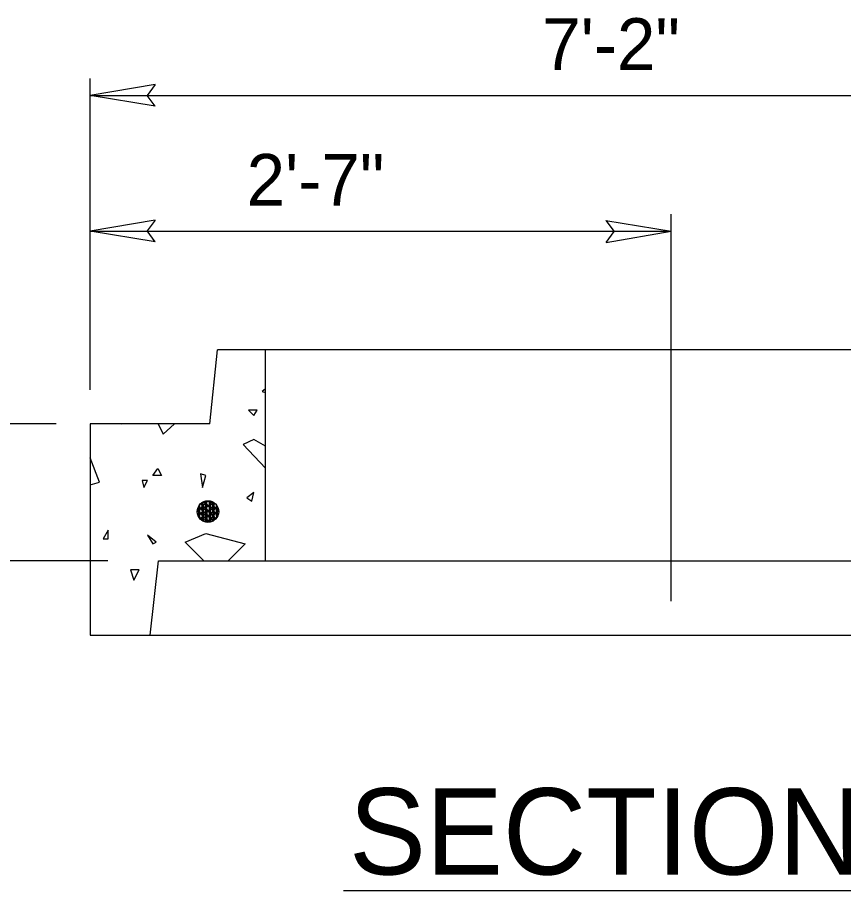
# Model space of a CAD drawing. Extents: x 1.8 to 9.1, y -6 to 4.
# Drawn here: x 5.032 to 5.989, y 0.893 to 1.904 of the extents above; entities that cross this region are included whole.
import ezdxf

# ---------------------------------------------------------------- set-up
doc = ezdxf.new("R2010")
doc.units = 0
for name, color, linetype in [('DETL-DIMS', 7, 'Continuous'), ('DETL-LINE', 7, 'Continuous'), ('DETL-NOTE', 7, 'Continuous'), ('DETL-PATT', 7, 'Continuous'), ('DETL-TITL', 7, 'Continuous')]:
    doc.layers.add(name, color=color, linetype=linetype)

msp = doc.modelspace()

# ---------------------------------------------------------------- linework, layer by layer
at = {"layer": 'DETL-DIMS'}
for p, q in [((5.1159, 1.4731), (5.1159, 1.8337)), ((5.1913, 1.8268), (5.1159, 1.8141)), ((5.1913, 1.8268), (5.1819, 1.8142)), ((5.1914, 1.8017), (5.1159, 1.8141)), ((5.1159, 1.8141), (6.7739, 1.8141)), ((5.1914, 1.8017), (5.1819, 1.8142)), ((5.1913, 1.6698), (5.1159, 1.6569)), ((5.1913, 1.6698), (5.1819, 1.6572)), ((5.7136, 1.6691), (5.7891, 1.6569)), ((5.7136, 1.6691), (5.7231, 1.6565)), ((5.7891, 1.2283), (5.7891, 1.6765)), ((5.1914, 1.6446), (5.1159, 1.6569)), ((5.1159, 1.6569), (5.7891, 1.6569)), ((5.1914, 1.6446), (5.1819, 1.6572)), ((5.7137, 1.6439), (5.7891, 1.6569)), ((5.7137, 1.6439), (5.7231, 1.6565)), ((5.0766, 1.4338), (4.9586, 1.4338)), ((5.1362, 1.275), (4.9586, 1.275))]:
    msp.add_line(p, q, dxfattribs=at)
at = {"layer": 'DETL-LINE'}
for p, q in [((5.2545, 1.4338), (5.2635, 1.5193)), ((6.3147, 1.5193), (5.2635, 1.5193)), ((5.319, 1.275), (5.319, 1.5193)), ((5.1159, 1.4338), (5.1159, 1.189)), ((5.2545, 1.4338), (5.1159, 1.4338)), ((5.2509, 1.3429), (5.2416, 1.3335)), ((5.2509, 1.3371), (5.2416, 1.3277)), ((5.243, 1.3241), (5.2429, 1.3374)), ((5.2523, 1.3269), (5.2429, 1.3362)), ((5.2526, 1.3273), (5.2433, 1.3366)), ((5.2538, 1.34), (5.2445, 1.3306)), ((5.2459, 1.3283), (5.2458, 1.3415)), ((5.2552, 1.3298), (5.2458, 1.3391)), ((5.246, 1.3242), (5.2459, 1.3374)), ((5.2556, 1.3303), (5.2461, 1.3396)), ((5.2471, 1.3283), (5.247, 1.3415)), ((5.2471, 1.3242), (5.2471, 1.3374)), ((5.2567, 1.343), (5.2474, 1.3336)), ((5.2568, 1.3371), (5.2475, 1.3277)), ((5.2581, 1.3328), (5.2488, 1.3421)), ((5.2582, 1.3269), (5.2488, 1.3362)), ((5.2585, 1.3332), (5.249, 1.3425)), ((5.2585, 1.3274), (5.249, 1.3367)), ((5.2501, 1.3283), (5.25, 1.3415)), ((5.2501, 1.3242), (5.25, 1.3374)), ((5.2596, 1.34), (5.2504, 1.3307)), ((5.2512, 1.3283), (5.2512, 1.3415)), ((5.2513, 1.3242), (5.2512, 1.3374)), ((5.2611, 1.3299), (5.2517, 1.3391)), ((5.2614, 1.3303), (5.2519, 1.3396)), ((5.2626, 1.3371), (5.2533, 1.3277)), ((5.2542, 1.3283), (5.2541, 1.3416)), ((5.2542, 1.3242), (5.2541, 1.3375)), ((5.264, 1.3328), (5.2546, 1.3421)), ((5.2643, 1.3332), (5.2548, 1.3425)), ((5.2554, 1.3283), (5.2553, 1.3416)), ((5.2554, 1.3242), (5.2553, 1.3375)), ((5.2583, 1.3284), (5.2582, 1.3416)), ((5.2583, 1.3242), (5.2583, 1.3375)), ((5.2595, 1.3284), (5.2594, 1.3416)), ((5.2595, 1.3242), (5.2594, 1.3375)), ((5.2495, 1.324), (5.24, 1.3333)), ((5.2497, 1.3244), (5.2403, 1.3337)), ((5.2524, 1.3211), (5.243, 1.3304)), ((5.2527, 1.3215), (5.2433, 1.3308)), ((5.2539, 1.3342), (5.2445, 1.3248)), ((5.2553, 1.324), (5.2459, 1.3333)), ((5.2556, 1.3244), (5.2462, 1.3337)), ((5.2568, 1.3313), (5.2475, 1.3218)), ((5.2582, 1.3211), (5.2488, 1.3304)), ((5.2585, 1.3215), (5.2491, 1.3308)), ((5.2501, 1.32), (5.25, 1.3333)), ((5.2597, 1.3342), (5.2504, 1.3248)), ((5.2513, 1.3201), (5.2512, 1.3333)), ((5.2611, 1.324), (5.2517, 1.3333)), ((5.2615, 1.3244), (5.252, 1.3338)), ((5.2626, 1.3314), (5.2533, 1.3219)), ((5.2542, 1.3201), (5.2541, 1.3333)), ((5.2554, 1.3201), (5.2553, 1.3333)), ((5.1853, 1.189), (5.1952, 1.275)), ((5.1952, 1.275), (6.6925, 1.275)), ((5.1159, 1.189), (6.7739, 1.189))]:
    msp.add_line(p, q, dxfattribs=at)
for points in [[(5.248, 1.34), (5.24, 1.3319)], [(5.2451, 1.3371), (5.24, 1.3319)], [(5.2494, 1.3298), (5.2413, 1.3378)], [(5.2465, 1.3327), (5.2413, 1.3378)], [(5.2436, 1.3356), (5.2413, 1.3378)], [(5.2497, 1.3302), (5.2416, 1.3383)], [(5.2468, 1.3331), (5.2416, 1.3383)], [(5.2438, 1.336), (5.2416, 1.3383)], [(5.2418, 1.3283), (5.2418, 1.3386)], [(5.2418, 1.3324), (5.2418, 1.3386)], [(5.2418, 1.3365), (5.2418, 1.3386)], [(5.2418, 1.3255), (5.2418, 1.3374)], [(5.243, 1.3283), (5.2429, 1.3402)], [(5.2429, 1.3324), (5.2429, 1.3402)], [(5.2429, 1.3365), (5.2429, 1.3402)], [(5.2523, 1.3327), (5.2438, 1.3411)], [(5.2494, 1.3356), (5.2438, 1.3411)], [(5.2465, 1.3386), (5.2438, 1.3411)], [(5.2526, 1.3332), (5.2442, 1.3415)], [(5.2497, 1.3361), (5.2442, 1.3415)], [(5.2467, 1.339), (5.2442, 1.3415)], [(5.2525, 1.3446), (5.2445, 1.3365)], [(5.2459, 1.3324), (5.2458, 1.3427)], [(5.2459, 1.3365), (5.2458, 1.3427)], [(5.2458, 1.3407), (5.2458, 1.3427)], [(5.2471, 1.3324), (5.247, 1.3433)], [(5.2471, 1.3365), (5.247, 1.3433)], [(5.247, 1.3407), (5.247, 1.3433)], [(5.2552, 1.3357), (5.2473, 1.3435)], [(5.2523, 1.3386), (5.2473, 1.3435)], [(5.2493, 1.3415), (5.2473, 1.3435)], [(5.2525, 1.3446), (5.2474, 1.3394)], [(5.2555, 1.3361), (5.2479, 1.3437)], [(5.2526, 1.339), (5.2479, 1.3437)], [(5.2496, 1.3419), (5.2479, 1.3437)], [(5.2501, 1.3324), (5.25, 1.3443)], [(5.25, 1.3365), (5.25, 1.3443)], [(5.25, 1.3407), (5.25, 1.3443)], [(5.2573, 1.3435), (5.2503, 1.3365)], [(5.2512, 1.3325), (5.2511, 1.3445)], [(5.2512, 1.3366), (5.2511, 1.3445)], [(5.2512, 1.3407), (5.2511, 1.3445)], [(5.2611, 1.3357), (5.2521, 1.3446)], [(5.2581, 1.3386), (5.2521, 1.3446)], [(5.2552, 1.3415), (5.2521, 1.3446)], [(5.2522, 1.3444), (5.2521, 1.3446)], [(5.2614, 1.3362), (5.2528, 1.3446)], [(5.2584, 1.3391), (5.2528, 1.3446)], [(5.2555, 1.3419), (5.2528, 1.3446)], [(5.2609, 1.3413), (5.2533, 1.3336)], [(5.2542, 1.3325), (5.2541, 1.3444)], [(5.2541, 1.3366), (5.2541, 1.3444)], [(5.2541, 1.3407), (5.2541, 1.3444)], [(5.2638, 1.3271), (5.2546, 1.3363)], [(5.264, 1.3277), (5.2549, 1.3367)], [(5.2553, 1.3325), (5.2552, 1.3442)], [(5.2553, 1.3366), (5.2552, 1.3442)], [(5.2553, 1.3407), (5.2552, 1.3442)], [(5.2634, 1.338), (5.2562, 1.3307)], [(5.2649, 1.3319), (5.2575, 1.3392)], [(5.2649, 1.3327), (5.2578, 1.3397)], [(5.2583, 1.3325), (5.2582, 1.3431)], [(5.2583, 1.3366), (5.2582, 1.3431)], [(5.2582, 1.3408), (5.2582, 1.3431)], [(5.2594, 1.3325), (5.2594, 1.3424)], [(5.2594, 1.3366), (5.2594, 1.3424)], [(5.2594, 1.3408), (5.2594, 1.3424)], [(5.2649, 1.3319), (5.2604, 1.3363)], [(5.2649, 1.3327), (5.2607, 1.3367)], [(5.2624, 1.3284), (5.2624, 1.3396)], [(5.2624, 1.3325), (5.2624, 1.3396)], [(5.2624, 1.3366), (5.2624, 1.3396)], [(5.2625, 1.3248), (5.2624, 1.3375)], [(5.2636, 1.3284), (5.2635, 1.3377)], [(5.2636, 1.3325), (5.2635, 1.3377)], [(5.2636, 1.3366), (5.2635, 1.3377)], [(5.2636, 1.3266), (5.2635, 1.3375)], [(5.2422, 1.3342), (5.24, 1.3319)], [(5.2465, 1.3268), (5.24, 1.3333)], [(5.2436, 1.3297), (5.24, 1.3333)], [(5.2407, 1.3327), (5.24, 1.3333)], [(5.2468, 1.3273), (5.2401, 1.334)], [(5.2438, 1.3302), (5.2401, 1.334)], [(5.241, 1.3331), (5.2401, 1.334)], [(5.2478, 1.3205), (5.2409, 1.3274)], [(5.2468, 1.3215), (5.2409, 1.3274)], [(5.2439, 1.3244), (5.2409, 1.3274)], [(5.241, 1.3273), (5.2409, 1.3274)], [(5.248, 1.3342), (5.241, 1.327)], [(5.2451, 1.3312), (5.241, 1.327)], [(5.2422, 1.3283), (5.241, 1.327)], [(5.2464, 1.3211), (5.2416, 1.326)], [(5.2464, 1.3211), (5.2416, 1.326)], [(5.2436, 1.3239), (5.2416, 1.326)], [(5.2418, 1.3255), (5.2418, 1.3332)], [(5.2418, 1.3255), (5.2418, 1.3291)], [(5.243, 1.3239), (5.2429, 1.3332)], [(5.243, 1.3239), (5.243, 1.3291)], [(5.2478, 1.3205), (5.2433, 1.325)], [(5.251, 1.3313), (5.2434, 1.3236)], [(5.248, 1.3283), (5.2434, 1.3236)], [(5.2452, 1.3254), (5.2434, 1.3236)], [(5.246, 1.3215), (5.2459, 1.3333)], [(5.246, 1.3215), (5.2459, 1.3292)], [(5.2537, 1.3197), (5.2459, 1.3275)], [(5.2544, 1.3198), (5.2462, 1.3279)], [(5.2539, 1.3284), (5.2467, 1.321)], [(5.251, 1.3254), (5.2467, 1.321)], [(5.2471, 1.3208), (5.2471, 1.3333)], [(5.2471, 1.3208), (5.2471, 1.3292)], [(5.2544, 1.3198), (5.2491, 1.325)], [(5.2501, 1.3198), (5.2501, 1.3292)], [(5.2513, 1.3197), (5.2512, 1.3292)], [(5.2597, 1.3284), (5.2512, 1.3197)], [(5.2569, 1.3255), (5.2512, 1.3197)], [(5.2583, 1.3211), (5.2517, 1.3275)], [(5.2587, 1.3213), (5.252, 1.3279)], [(5.2543, 1.3198), (5.2542, 1.3292)], [(5.2616, 1.3236), (5.2547, 1.3304)], [(5.2619, 1.324), (5.2549, 1.3309)], [(5.2554, 1.32), (5.2554, 1.3292)], [(5.2648, 1.3335), (5.2562, 1.3248)], [(5.2638, 1.3271), (5.2575, 1.3334)], [(5.264, 1.3277), (5.2578, 1.3338)], [(5.2583, 1.3211), (5.2583, 1.3334)], [(5.2583, 1.3211), (5.2583, 1.3292)], [(5.2635, 1.3263), (5.2583, 1.3211)], [(5.2627, 1.3255), (5.2583, 1.3211)], [(5.2648, 1.3335), (5.2591, 1.3278)], [(5.2635, 1.3263), (5.2592, 1.3219)], [(5.2595, 1.3219), (5.2594, 1.3334)], [(5.2595, 1.3219), (5.2595, 1.3292)], [(5.2635, 1.3263), (5.2621, 1.3249)], [(5.2625, 1.3248), (5.2624, 1.3334)], [(5.2625, 1.3248), (5.2624, 1.3292)], [(5.2636, 1.3266), (5.2636, 1.3334)], [(5.2636, 1.3266), (5.2636, 1.3292)], [(5.2464, 1.3211), (5.243, 1.3245)], [(5.2464, 1.3211), (5.2459, 1.3216)], [(5.2478, 1.3205), (5.2462, 1.322)], [(5.2481, 1.3225), (5.2467, 1.321)], [(5.2537, 1.3197), (5.2488, 1.3246)], [(5.2539, 1.3225), (5.2512, 1.3197)], [(5.2598, 1.3226), (5.2583, 1.3211)]]:
    msp.add_lwpolyline(points, dxfattribs=at)
msp.add_circle((5.2524, 1.3321), 0.0125, dxfattribs=at)
at = {"layer": 'DETL-PATT'}
for points in [[(5.319, 1.4741), (5.3154, 1.4712), (5.319, 1.47)], [(5.1521, 1.4338), (5.1527, 1.4335), (5.1526, 1.4338)], [(5.1946, 1.4338), (5.2003, 1.4217), (5.2135, 1.4338)], [(5.319, 1.4078), (5.3055, 1.4156), (5.2932, 1.4099), (5.319, 1.3823)], [(5.1159, 1.3632), (5.1268, 1.366), (5.1159, 1.3942)], [(5.2475, 1.275), (5.2258, 1.2967), (5.2499, 1.3066), (5.2956, 1.2948), (5.2758, 1.275)]]:
    msp.add_lwpolyline(points, dxfattribs=at)
for points in [[(5.2994, 1.4495), (5.3055, 1.4434), (5.3093, 1.4495)], [(5.1942, 1.3821), (5.1984, 1.374), (5.1885, 1.374)], [(5.2437, 1.3759), (5.2461, 1.3599), (5.2499, 1.374)], [(5.1763, 1.3679), (5.1782, 1.3599), (5.1824, 1.3679)], [(5.2975, 1.3481), (5.3032, 1.3443), (5.3055, 1.3542)], [(5.1367, 1.3104), (5.131, 1.3005), (5.1367, 1.3005)], [(5.1885, 1.2948), (5.1923, 1.2967), (5.1824, 1.3047)], [(5.1626, 1.2646), (5.1664, 1.2528), (5.1725, 1.2646)]]:
    msp.add_lwpolyline(points, close=True, dxfattribs=at)
at = {"layer": 'DETL-TITL'}
msp.add_line((5.4096, 0.8931), (6.4614, 0.8931), dxfattribs=at)

# ---------------------------------------------------------------- texts
at = {"layer": 'DETL-NOTE'}
for s, p in [('7\'-2"', (5.6397, 1.8436)), ('2\'-7"', (5.2972, 1.6863))]:
    msp.add_text(s, height=0.05998, dxfattribs=at).set_placement(p)
at = {"layer": 'DETL-TITL'}
msp.add_text('SECTION A-A', height=0.099994, dxfattribs=at).set_placement((5.4158, 0.9117))

doc.saveas('drawing.dxf')
